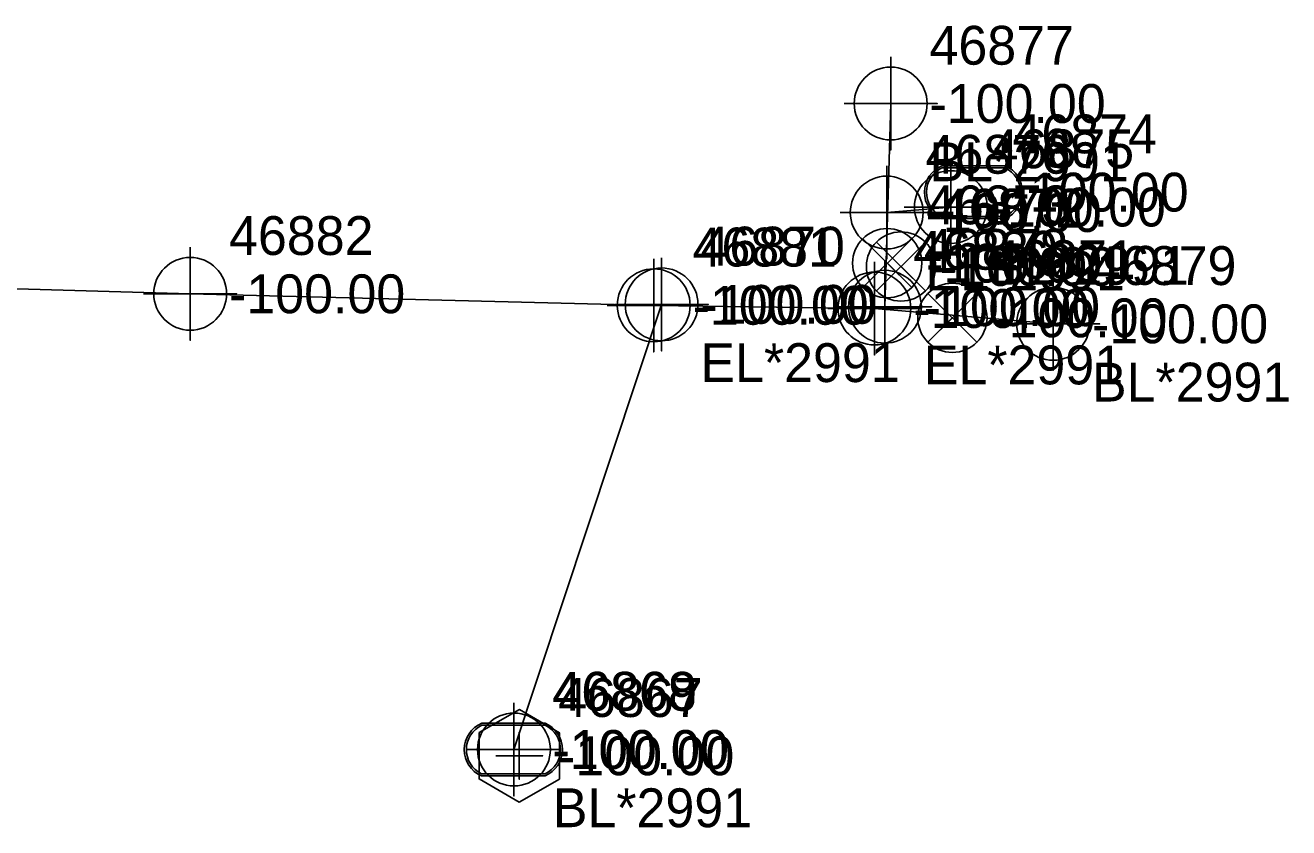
# Model space of a CAD drawing. Extents: x 2083698 to 2094313, y 743246 to 752873.
# Drawn here: x 2092783.1 to 2092864.4, y 747052 to 747103.6 of the extents above; entities that cross this region are included whole.
import ezdxf

# ---------------------------------------------------------------- set-up
doc = ezdxf.new("R2010")
doc.units = 0
for name, color, linetype in [('COGO Default Point Number', 7, 'Continuous'), ('Default Symbol Cogo Comment', 7, 'Continuous'), ('Exist Guardrail', 7, 'Continuous'), ('Exist Property Line', 7, 'Continuous'), ('Exist Right of Way Line', 7, 'Continuous'), ('Exist Right of Way Monument CELL', 7, 'Continuous'), ('Exist Right of Way Width CELL', 7, 'Continuous'), ('Exist Roads EOP', 7, 'Continuous'), ('Exist Roads EOP Cogo Comment', 7, 'Continuous'), ('Exist Roads EOP Cogo Elevation', 7, 'Continuous'), ('Exist Roads EOP Leader', 7, 'Continuous'), ('Exist Roads EOP Text', 7, 'Continuous'), ('Exist Utilities Other Pole CELL', 7, 'Continuous'), ('Exist Utilities Water UG Line SUE LOS B', 7, 'Continuous')]:
    doc.layers.add(name, color=color, linetype=linetype)

msp = doc.modelspace()

# ---------------------------------------------------------------- linework, layer by layer
at = {"layer": 'COGO Default Point Number'}
for points in [[(2092838.786, 747101.605), (2092838.786, 747095.605), (2092838.786, 747098.605), (2092841.786, 747098.605), (2092835.786, 747098.605)], [(2092842.659, 747094.937), (2092842.659, 747088.937), (2092842.659, 747091.937), (2092845.659, 747091.937), (2092839.659, 747091.937)], [(2092838.532, 747094.585), (2092838.532, 747088.585), (2092838.532, 747091.585), (2092841.532, 747091.585), (2092835.532, 747091.585)], [(2092793.704, 747089.354), (2092793.704, 747083.354), (2092793.704, 747086.354), (2092796.704, 747086.354), (2092790.704, 747086.354)], [(2092823.535, 747088.612), (2092823.535, 747082.612), (2092823.535, 747085.612), (2092826.535, 747085.612), (2092820.535, 747085.612)], [(2092824.041, 747088.674), (2092824.041, 747082.674), (2092824.041, 747085.674), (2092827.041, 747085.674), (2092821.041, 747085.674)], [(2092837.741, 747088.406), (2092837.741, 747082.406), (2092837.741, 747085.406), (2092840.741, 747085.406), (2092834.741, 747085.406)], [(2092838.418, 747088.525), (2092838.418, 747082.525), (2092838.418, 747085.525), (2092841.418, 747085.525), (2092835.418, 747085.525)], [(2092849.241, 747087.42), (2092849.241, 747081.42), (2092849.241, 747084.42), (2092852.241, 747084.42), (2092846.241, 747084.42)], [(2092814.541, 747060.016), (2092814.541, 747054.016), (2092814.541, 747057.016), (2092817.541, 747057.016), (2092811.541, 747057.016)]]:
    msp.add_lwpolyline(points, dxfattribs=at)
for centre in [(2092838.786, 747098.605), (2092842.659, 747091.937), (2092838.532, 747091.585), (2092793.704, 747086.354), (2092823.535, 747085.612), (2092824.041, 747085.674), (2092837.741, 747085.406), (2092838.418, 747085.525), (2092849.241, 747084.42), (2092814.541, 747057.016)]:
    msp.add_circle(centre, 2.344, dxfattribs=at)
at = {"layer": 'Exist Guardrail'}
for p, q in [((2092844.123, 747092.899), (2092844.123, 747092.899)), ((2092814.508, 747057.012), (2092814.508, 747057.012))]:
    msp.add_line(p, q, dxfattribs=at)
for points in [[(2092842.086, 747094.599), (2092846.161, 747094.599)], [(2092842.086, 747094.461), (2092846.161, 747094.461)], [(2092846.161, 747091.336), (2092842.061, 747091.336)], [(2092846.161, 747091.199), (2092842.061, 747091.199)], [(2092812.47, 747058.712), (2092816.545, 747058.712)], [(2092812.47, 747058.575), (2092816.545, 747058.575)], [(2092816.545, 747055.45), (2092812.445, 747055.45)], [(2092816.545, 747055.312), (2092812.445, 747055.312)]]:
    msp.add_lwpolyline(points, dxfattribs=at)
for centre, radius, start, end in [((2092842.816, 747092.893), 1.855, 113.17804, 245.97939), ((2092842.827, 747092.893), 1.735, 115.30093, 243.78236), ((2092845.416, 747092.899), 1.856, 293.64832, 66.30838), ((2092845.428, 747092.899), 1.726, 295.12717, 64.87283), ((2092813.201, 747057.007), 1.855, 113.17804, 245.97939), ((2092813.212, 747057.006), 1.735, 115.30093, 243.78236), ((2092815.801, 747057.013), 1.856, 293.64832, 66.30838), ((2092815.813, 747057.012), 1.726, 295.12717, 64.87283)]:
    msp.add_arc(centre, radius, start, end, dxfattribs=at)
at = {"layer": 'Exist Roads EOP'}
for points in [[(2092840.138, 747089.902), (2092836.988, 747086.752), (2092838.563, 747088.327), (2092840.138, 747086.752), (2092836.988, 747089.902)], [(2092841.024, 747089.688), (2092837.874, 747086.538), (2092839.449, 747088.113), (2092841.024, 747086.538), (2092837.874, 747089.688)], [(2092844.335, 747086.381), (2092841.185, 747083.231), (2092842.76, 747084.806), (2092844.335, 747083.231), (2092841.185, 747086.381)]]:
    msp.add_lwpolyline(points, dxfattribs=at)
for centre in [(2092838.563, 747088.327), (2092839.449, 747088.113), (2092842.76, 747084.806)]:
    msp.add_circle(centre, 2.227, dxfattribs=at)
at = {"layer": 'Exist Roads EOP Cogo Elevation'}
msp.add_line((2092814.885, 747056.611), (2092814.885, 747056.611), dxfattribs=at)
msp.add_lwpolyline([(2092812.307, 747058.105), (2092812.301, 747055.125), (2092814.88, 747053.631), (2092817.463, 747055.116), (2092817.468, 747058.096), (2092814.89, 747059.59)], close=True, dxfattribs=at)
msp.add_lwpolyline([(2092814.885, 747058.123), (2092814.885, 747055.098), (2092814.885, 747056.611), (2092816.397, 747056.611), (2092813.372, 747056.611)], dxfattribs=at)
at = {"layer": 'Exist Utilities Water UG Line SUE LOS B'}
for p, q in [((2092838.786, 747098.605), (2092838.418, 747085.525)), ((2092842.659, 747091.937), (2092838.532, 747091.585)), ((2092814.541, 747057.016), (2092824.041, 747085.674))]:
    msp.add_line(p, q, dxfattribs=at)
msp.add_lwpolyline([(2092703.305, 747089.202), (2092712.4, 747089.811), (2092722.88, 747089.471), (2092752.936, 747087.633), (2092768.412, 747087.082), (2092793.704, 747086.354), (2092823.535, 747085.612), (2092837.741, 747085.406), (2092849.241, 747084.42)], dxfattribs=at)

# ---------------------------------------------------------------- texts
at = {"layer": 'Default Symbol Cogo Comment'}
for p in [(2092846.623, 747091.649), (2092817.008, 747055.762)]:
    msp.add_text('-100.00', height=2.5, dxfattribs=at).set_placement(p)
at = {"layer": 'Exist Property Line'}
for p in [(2092841.286, 747097.355), (2092841.032, 747090.335), (2092845.159, 747090.687), (2092796.204, 747085.104), (2092826.035, 747084.362), (2092826.541, 747084.424), (2092840.918, 747084.275), (2092840.241, 747084.156), (2092851.741, 747083.17), (2092817.041, 747055.766)]:
    msp.add_text('-100.00', height=2.5, dxfattribs=at).set_placement(p)
at = {"layer": 'Exist Right of Way Line'}
for s, p in [('46877', (2092841.286, 747101.105)), ('46876', (2092841.032, 747094.085)), ('46875', (2092845.159, 747094.437)), ('46882', (2092796.204, 747088.854)), ('46881', (2092826.035, 747088.112)), ('46870', (2092826.541, 747088.174)), ('46880', (2092840.241, 747087.906)), ('46878', (2092840.918, 747088.025)), ('46879', (2092851.741, 747086.92)), ('46869', (2092817.041, 747059.516))]:
    msp.add_text(s, height=2.5, dxfattribs=at).set_placement(p)
at = {"layer": 'Exist Right of Way Monument CELL'}
msp.add_text('-100.00', height=2.5, dxfattribs=at).set_placement((2092817.385, 747055.361))
at = {"layer": 'Exist Right of Way Width CELL'}
for s, p in [('BL*2991', (2092841.286, 747093.605)), ('BL*2991', (2092845.159, 747086.937)), ('EL*2991', (2092841.032, 747086.585)), ('EL*2991', (2092826.541, 747080.674)), ('EL*2991', (2092840.918, 747080.525)), ('BL*2991', (2092851.741, 747079.42)), ('BL*2991', (2092817.041, 747052.016))]:
    msp.add_text(s, height=2.5, dxfattribs=at).set_placement(p)
at = {"layer": 'Exist Roads EOP Cogo Comment'}
msp.add_text('46867', height=2.5, dxfattribs=at).set_placement((2092817.385, 747059.111))
at = {"layer": 'Exist Roads EOP Leader'}
for p in [(2092841.063, 747087.077), (2092841.949, 747086.863), (2092845.26, 747083.556)]:
    msp.add_text('-100.00', height=2.5, dxfattribs=at).set_placement(p)
at = {"layer": 'Exist Roads EOP Text'}
for s, p in [('46873', (2092841.063, 747090.827)), ('46872', (2092841.949, 747090.613)), ('46871', (2092845.26, 747087.306))]:
    msp.add_text(s, height=2.5, dxfattribs=at).set_placement(p)
at = {"layer": 'Exist Utilities Other Pole CELL'}
for s, p in [('46874', (2092846.623, 747095.399)), ('46868', (2092817.008, 747059.512))]:
    msp.add_text(s, height=2.5, dxfattribs=at).set_placement(p)

doc.saveas('drawing.dxf')
